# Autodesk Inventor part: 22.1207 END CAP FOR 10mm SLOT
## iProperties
Created: 2007-05
Part Number: 22.1207 END CAP FOR 10mm SLOT
Material: ABS Plastic
Document SubType Name: Modeling
Designer: Andy Moles
Mass: 1.36668 g
Surface Area: 30.2644 cm^2
Volume: 1.28932 cm^3
Density: 1.06 g/cm^3
Author: Andy Moles
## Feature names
1. Extrusion1
2. Extrusion2
3. Mirror1
4. Fillet1
5. Fillet2
